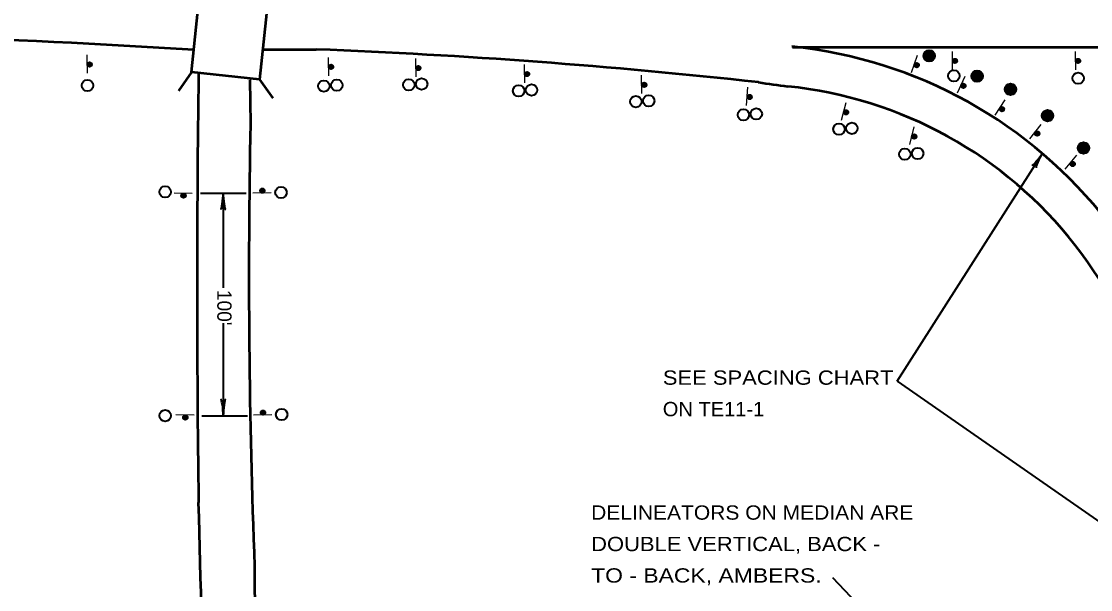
# Model space of a CAD drawing. Extents: x 393 to 1249, y -102 to 530.
# Drawn here: x 840.2 to 1022, y 229.1 to 325.7 of the extents above; entities that cross this region are included whole.
import ezdxf
from ezdxf.enums import TextEntityAlignment as Align

# ---------------------------------------------------------------- set-up
doc = ezdxf.new("R2010")
doc.units = 0
doc.header["$LTSCALE"] = 0.97
doc.layers.add('1', color=7, linetype='Continuous', lineweight=40)
doc.layers.add('4', color=7, linetype='Continuous', lineweight=25)

msp = doc.modelspace()

# ---------------------------------------------------------------- linework, layer by layer
at = {"layer": '1', "lineweight": 53}
for p, q in [((881.1775, 320.8992), (890.3153, 320.8992)), ((971.3426, 321.288), (1117.739, 321.288)), ((869.0836, 317.0209), (866.8533, 313.8363)), ((878.9941, 315.7335), (879.1249, 308.2401)), ((880.6838, 315.8016), (882.914, 312.6169))]:
    msp.add_line(p, q, dxfattribs=at)
at = {"layer": '1', "lineweight": 35}
for p, q in [((989.1144, 264.4924), (1013.9183, 303.3247)), ((870.6226, 296.465), (878.3986, 296.465)), ((874.4854, 296.465), (874.4854, 280.3528)), ((874.4854, 274.3552), (874.4854, 258.6495)), ((989.1144, 264.4924), (1038.9254, 229.9296)), ((870.8259, 258.6495), (878.6019, 258.6495)), ((978.1356, 231.1495), (1018.5944, 188.6576))]:
    msp.add_line(p, q, dxfattribs=at)
at = {"layer": '1', "lineweight": 53}
msp.add_lwpolyline([(871.7253, 342.1545), (883.3254, 340.935), (880.6838, 315.8016), (869.0836, 317.0209)], close=True, dxfattribs=at)
at = {"layer": '1'}
for centre, radius in [((994.5904, 319.7989), 0.972), ((994.5773, 319.8416), 0.8529), ((994.5646, 319.8162), 0.7878), ((994.5773, 319.7781), 0.7017), ((994.501, 319.524), 0.6228), ((994.5646, 319.8544), 0.5846), ((994.7171, 319.6637), 0.6414), ((994.5392, 319.7781), 0.4322), ((994.6408, 319.7018), 0.5216), ((994.59, 320.0322), 0.3831), ((994.5645, 319.8416), 0.3558), ((994.8187, 319.5621), 0.5762), ((851.7557, 318.3289), 0.3791), ((851.7461, 318.319), 0.35), ((851.7558, 318.3192), 0.3305), ((851.7748, 318.3487), 0.3402), ((851.7557, 318.3289), 0.3013), ((851.7557, 318.3289), 0.2819), ((851.7558, 318.3192), 0.2722), ((851.7558, 318.3192), 0.2527), ((851.7656, 318.3194), 0.2335), ((851.7753, 318.3195), 0.2138), ((851.7753, 318.3195), 0.1944), ((851.7562, 318.2998), 0.1555), ((851.7947, 318.3199), 0.175), ((851.756, 318.3095), 0.1069), ((851.8145, 318.3008), 0.1555), ((851.824, 318.3107), 0.1461), ((851.8339, 318.3011), 0.1166), ((851.8437, 318.3013), 0.0977), ((851.8534, 318.3015), 0.0778), ((851.7922, 318.4657), 0.00972), ((851.8728, 318.3018), 0.0583), ((851.8922, 318.3021), 0.0389), ((851.9117, 318.3025), 0.0194), ((892.8238, 317.9223), 0.3791), ((992.4465, 318.2232), 0.3791), ((992.4342, 318.2172), 0.35), ((992.4434, 318.214), 0.3305), ((992.4713, 318.2353), 0.3402), ((992.4465, 318.2232), 0.3013), ((992.4465, 318.2232), 0.2819), ((992.4434, 318.214), 0.2722), ((992.4434, 318.214), 0.2527), ((992.4526, 318.2109), 0.2335), ((992.4618, 318.2077), 0.2138), ((992.4618, 318.2077), 0.1944), ((992.4371, 318.1956), 0.1555), ((992.4801, 318.2014), 0.175), ((992.4402, 318.2048), 0.1069), ((992.4922, 318.1767), 0.1555), ((992.5046, 318.1827), 0.1461), ((992.5276, 318.3392), 0.00972), ((994.1579, 319.5748), 0.3923), ((994.59, 319.8416), 0.2049), ((994.59, 319.8162), 0.0508), ((998.9504, 318.9388), 0.3791), ((998.9409, 318.929), 0.35), ((998.9506, 318.9291), 0.3305), ((998.9695, 318.9586), 0.3402), ((998.9504, 318.9388), 0.3013), ((998.9504, 318.9388), 0.2819), ((998.9506, 318.9291), 0.2722), ((998.9506, 318.9291), 0.2527), ((998.9603, 318.9293), 0.2335), ((998.97, 318.9295), 0.2138), ((998.97, 318.9295), 0.1944), ((998.9509, 318.9097), 0.1555), ((998.9895, 318.9298), 0.175), ((998.9508, 318.9194), 0.1069), ((999.0092, 318.9107), 0.1555), ((999.0188, 318.9206), 0.1461), ((999.0287, 318.9111), 0.1166), ((999.0384, 318.9112), 0.0977), ((999.0481, 318.9114), 0.0778), ((998.9869, 319.0756), 0.00972), ((999.0675, 318.9117), 0.0583), ((999.087, 318.9121), 0.0389), ((999.1064, 318.9124), 0.0194), ((1019.8911, 318.9388), 0.3791), ((1019.8816, 318.929), 0.35), ((1019.8913, 318.9291), 0.3305), ((1019.9102, 318.9586), 0.3402), ((1019.8911, 318.9388), 0.3013), ((1019.8911, 318.9388), 0.2819), ((1019.8913, 318.9291), 0.2722), ((1019.8913, 318.9291), 0.2527), ((1019.901, 318.9293), 0.2335), ((1019.9107, 318.9295), 0.2138), ((1019.9107, 318.9295), 0.1944), ((1019.8916, 318.9097), 0.1555), ((1019.9301, 318.9298), 0.175), ((1019.8914, 318.9194), 0.1069), ((1019.9499, 318.9107), 0.1555), ((1019.9595, 318.9206), 0.1461), ((1019.9694, 318.9111), 0.1166), ((1019.9791, 318.9112), 0.0977), ((1019.9888, 318.9114), 0.0778), ((1019.9276, 319.0756), 0.00972), ((1020.0082, 318.9117), 0.0583), ((1020.0277, 318.9121), 0.0389), ((1020.0471, 318.9124), 0.0194), ((892.8143, 317.9124), 0.35), ((892.824, 317.9126), 0.3305), ((892.8429, 317.9421), 0.3402), ((892.8238, 317.9223), 0.3013), ((892.8238, 317.9223), 0.2819), ((892.824, 317.9126), 0.2722), ((892.824, 317.9126), 0.2527), ((892.8337, 317.9128), 0.2335), ((892.8434, 317.9129), 0.2138), ((892.8434, 317.9129), 0.1944), ((892.8243, 317.8931), 0.1555), ((892.8629, 317.9133), 0.175), ((892.8241, 317.9029), 0.1069), ((892.8826, 317.8942), 0.1555), ((892.8922, 317.904), 0.1461), ((892.9021, 317.8945), 0.1166), ((892.9118, 317.8947), 0.0977), ((892.9215, 317.8948), 0.0778), ((892.8603, 318.059), 0.00972), ((892.9409, 317.8952), 0.0583), ((892.9604, 317.8955), 0.0389), ((892.9798, 317.8959), 0.0194), ((907.6653, 317.719), 0.3791), ((907.6557, 317.7091), 0.35), ((907.6654, 317.7093), 0.3305), ((907.6844, 317.7388), 0.3402), ((907.6653, 317.719), 0.3013), ((907.6653, 317.719), 0.2819), ((907.6654, 317.7093), 0.2722), ((907.6654, 317.7093), 0.2527), ((907.6752, 317.7094), 0.2335), ((907.6849, 317.7096), 0.2138), ((907.6849, 317.7096), 0.1944), ((907.6658, 317.6898), 0.1555), ((907.7043, 317.7099), 0.175), ((907.6656, 317.6996), 0.1069), ((907.7241, 317.6909), 0.1555), ((907.7336, 317.7007), 0.1461), ((907.7435, 317.6912), 0.1166), ((907.7533, 317.6914), 0.0977), ((907.763, 317.6915), 0.0778), ((907.7018, 317.8557), 0.00972), ((907.7824, 317.6919), 0.0583), ((907.8018, 317.6922), 0.0389), ((907.8213, 317.6925), 0.0194), ((926.1663, 316.7024), 0.3791), ((926.1568, 316.6926), 0.35), ((926.1665, 316.6927), 0.3305), ((926.1854, 316.7222), 0.3402), ((926.1663, 316.7024), 0.3013), ((926.1663, 316.7024), 0.2819), ((926.1665, 316.6927), 0.2722), ((926.1665, 316.6927), 0.2527), ((926.1762, 316.6929), 0.2335), ((926.1859, 316.6931), 0.2138), ((926.1859, 316.6931), 0.1944), ((926.1668, 316.6733), 0.1555), ((926.2054, 316.6934), 0.175), ((926.1667, 316.683), 0.1069), ((926.2251, 316.6743), 0.1555), ((926.2347, 316.6842), 0.1461), ((926.2446, 316.6746), 0.1166), ((926.2543, 316.6748), 0.0977), ((926.264, 316.675), 0.0778), ((926.2028, 316.8392), 0.00972), ((926.2835, 316.6753), 0.0583), ((926.3029, 316.6757), 0.0389), ((926.3223, 316.676), 0.0194), ((992.5106, 318.1703), 0.1166), ((992.5198, 318.1672), 0.0977), ((992.529, 318.164), 0.0778), ((992.5473, 318.1577), 0.0583), ((992.5657, 318.1513), 0.0389), ((992.5841, 318.145), 0.0194), ((998.7836, 316.3927), 0.972), ((1002.7227, 316.3427), 0.972), ((1002.7096, 316.3854), 0.8529), ((1002.2902, 316.1186), 0.3923), ((1002.6969, 316.36), 0.7878), ((1002.7096, 316.3219), 0.7017), ((1002.6334, 316.0678), 0.6228), ((1002.6969, 316.3982), 0.5846), ((1002.8494, 316.2075), 0.6414), ((1002.6715, 316.3219), 0.4322), ((1002.7731, 316.2457), 0.5216), ((1002.7223, 316.576), 0.3831), ((1002.6969, 316.3855), 0.3558), ((1002.951, 316.1059), 0.5762), ((1002.7223, 316.3855), 0.2049), ((1019.9276, 315.9861), 0.972), ((851.3854, 314.7663), 0.972), ((891.6088, 314.6635), 0.972), ((893.8033, 314.805), 0.972), ((906.0438, 314.8667), 0.972), ((908.2383, 315.0083), 0.972), ((924.748, 313.8502), 0.972), ((926.9425, 313.9917), 0.972), ((946.0905, 314.8726), 0.3791), ((946.0809, 314.8628), 0.35), ((946.0906, 314.8629), 0.3305), ((946.1096, 314.8924), 0.3402), ((946.0905, 314.8726), 0.3013), ((946.0905, 314.8726), 0.2819), ((946.0906, 314.8629), 0.2722), ((946.0906, 314.8629), 0.2527), ((946.1004, 314.8631), 0.2335), ((946.1101, 314.8633), 0.2138), ((946.1101, 314.8633), 0.1944), ((946.091, 314.8435), 0.1555), ((946.1295, 314.8636), 0.175), ((946.0908, 314.8532), 0.1069), ((946.1493, 314.8445), 0.1555), ((946.1588, 314.8544), 0.1461), ((946.1687, 314.8449), 0.1166), ((946.1784, 314.845), 0.0977), ((946.1882, 314.8452), 0.0778), ((946.127, 315.0094), 0.00972), ((946.2076, 314.8455), 0.0583), ((946.227, 314.8459), 0.0389), ((946.2465, 314.8462), 0.0194), ((1000.3856, 314.7027), 0.3791), ((1000.3728, 314.6977), 0.35), ((1000.3817, 314.6938), 0.3305), ((1000.4113, 314.7125), 0.3402), ((1000.3856, 314.7027), 0.3013), ((1000.3856, 314.7027), 0.2819), ((1000.3817, 314.6938), 0.2722), ((1000.3817, 314.6938), 0.2527), ((1000.3906, 314.6898), 0.2335), ((1000.3994, 314.6859), 0.2138), ((1000.3994, 314.6859), 0.1944), ((1000.3738, 314.676), 0.1555), ((1000.4172, 314.678), 0.175), ((1000.3777, 314.6849), 0.1069), ((1000.4271, 314.6523), 0.1555), ((1000.4399, 314.6572), 0.1461), ((1000.4448, 314.6444), 0.1166), ((1000.4537, 314.6404), 0.0977), ((1000.4626, 314.6365), 0.0778), ((1000.4803, 314.6286), 0.0583), ((1000.4981, 314.6207), 0.0389), ((1000.4765, 314.8112), 0.00972), ((1002.7223, 316.36), 0.0508), ((1008.4154, 314.1063), 0.972), ((1008.4023, 314.149), 0.8529), ((1008.3896, 314.1236), 0.7878), ((1008.4023, 314.0855), 0.7017), ((1008.3896, 314.1618), 0.5846), ((1008.415, 314.3396), 0.3831), ((944.6722, 312.0204), 0.972), ((946.8667, 312.1619), 0.972), ((964.0243, 312.8095), 0.3791), ((964.0139, 312.8005), 0.35), ((964.0236, 312.7998), 0.3305), ((964.0451, 312.8275), 0.3402), ((964.0243, 312.8095), 0.3013), ((964.0243, 312.8095), 0.2819), ((964.0236, 312.7998), 0.2722), ((964.0236, 312.7998), 0.2527), ((964.0333, 312.7991), 0.2335), ((964.043, 312.7984), 0.2138), ((964.043, 312.7984), 0.1944), ((964.0223, 312.7804), 0.1555), ((964.0624, 312.7971), 0.175), ((964.023, 312.7901), 0.1069), ((964.0805, 312.7763), 0.1555), ((964.0908, 312.7853), 0.1461), ((964.0999, 312.775), 0.1166), ((964.1095, 312.7743), 0.0977), ((964.1192, 312.7736), 0.0778), ((964.0726, 312.9425), 0.00972), ((1000.5159, 314.6128), 0.0194), ((1007.9829, 313.8822), 0.3923), ((1008.326, 313.8314), 0.6228), ((1008.5421, 313.9711), 0.6414), ((1008.3642, 314.0855), 0.4322), ((1008.4658, 314.0092), 0.5216), ((1008.3895, 314.149), 0.3558), ((1008.6437, 313.8695), 0.5762), ((1008.415, 314.149), 0.2049), ((1008.415, 314.1236), 0.0508), ((964.1386, 312.7723), 0.0583), ((964.158, 312.7709), 0.0389), ((964.1774, 312.7695), 0.0194), ((1006.9475, 310.7465), 0.3791), ((1006.934, 310.7438), 0.35), ((1006.9421, 310.7384), 0.3305), ((1006.9745, 310.7517), 0.3402), ((1006.9475, 310.7465), 0.3013), ((1006.9475, 310.7465), 0.2819), ((962.9699, 309.784), 0.972), ((965.1644, 309.9256), 0.972), ((980.4372, 310.2066), 0.3791), ((980.4255, 310.1995), 0.35), ((980.4349, 310.1972), 0.3305), ((980.4608, 310.2207), 0.3402), ((980.4372, 310.2066), 0.3013), ((980.4372, 310.2066), 0.2819), ((980.4349, 310.1972), 0.2722), ((980.4349, 310.1972), 0.2527), ((980.4443, 310.1948), 0.2335), ((980.4538, 310.1925), 0.2138), ((980.4538, 310.1925), 0.1944), ((980.4302, 310.1783), 0.1555), ((980.4726, 310.1878), 0.175), ((980.4325, 310.1877), 0.1069), ((980.4868, 310.1642), 0.1555), ((980.4986, 310.1713), 0.1461), ((980.5056, 310.1595), 0.1166), ((980.5151, 310.1571), 0.0977), ((980.5245, 310.1548), 0.0778), ((980.5434, 310.1501), 0.0583), ((980.5079, 310.3292), 0.00972), ((980.5622, 310.1454), 0.0389), ((980.5811, 310.1407), 0.0194), ((1006.9421, 310.7384), 0.2722), ((1006.9421, 310.7384), 0.2527), ((1006.9501, 310.733), 0.2335), ((1006.9582, 310.7275), 0.2138), ((1006.9582, 310.7275), 0.1944), ((1006.9312, 310.7223), 0.1555), ((1006.9743, 310.7167), 0.175), ((1006.9796, 310.6897), 0.1555), ((1006.9366, 310.7303), 0.1069), ((1006.993, 310.6923), 0.1461), ((1006.9957, 310.6788), 0.1166), ((1007.0037, 310.6734), 0.0977), ((1007.0118, 310.6679), 0.0778), ((1007.0279, 310.6571), 0.0583), ((1007.044, 310.6462), 0.0389), ((1007.0601, 310.6353), 0.0194), ((1007.0558, 310.8375), 0.00972), ((1014.718, 309.6335), 0.972), ((1014.7048, 309.6762), 0.8529), ((1014.2855, 309.4094), 0.3923), ((1014.6921, 309.6508), 0.7878), ((1014.7048, 309.6127), 0.7017), ((1014.6286, 309.3585), 0.6228), ((1014.6921, 309.6889), 0.5846), ((1014.8446, 309.4983), 0.6414), ((1014.6667, 309.6127), 0.4322), ((1014.7683, 309.5364), 0.5216), ((1014.7175, 309.8668), 0.3831), ((1014.6921, 309.6762), 0.3558), ((1014.9463, 309.3967), 0.5762), ((1014.7176, 309.6762), 0.2049), ((1014.7175, 309.6508), 0.0508), ((979.2346, 307.3443), 0.972), ((981.4291, 307.4859), 0.972), ((992.0217, 306.0843), 0.3791), ((992.0099, 306.0772), 0.35), ((992.0194, 306.0748), 0.3305), ((992.0453, 306.0984), 0.3402), ((992.0217, 306.0843), 0.3013), ((992.0217, 306.0843), 0.2819), ((992.0194, 306.0748), 0.2722), ((992.0194, 306.0748), 0.2527), ((992.0288, 306.0725), 0.2335), ((992.0382, 306.0701), 0.2138), ((992.0382, 306.0701), 0.1944), ((992.0147, 306.056), 0.1555), ((992.0571, 306.0654), 0.175), ((992.017, 306.0654), 0.1069), ((992.0712, 306.0419), 0.1555), ((992.083, 306.049), 0.1461), ((992.0901, 306.0372), 0.1166), ((992.0995, 306.0348), 0.0977), ((992.109, 306.0325), 0.0778), ((992.1278, 306.0278), 0.0583), ((992.0924, 306.2069), 0.00972), ((992.1467, 306.0231), 0.0389), ((992.1656, 306.0184), 0.0194), ((1012.9435, 306.5887), 0.3791), ((1012.9299, 306.5873), 0.35), ((1012.9374, 306.5812), 0.3305), ((1012.9709, 306.5916), 0.3402), ((1012.9435, 306.5887), 0.3013), ((1012.9435, 306.5887), 0.2819), ((1012.9374, 306.5812), 0.2722), ((1012.9374, 306.5812), 0.2527), ((1012.945, 306.575), 0.2335), ((1012.9525, 306.5689), 0.2138), ((1012.9525, 306.5689), 0.1944), ((1012.9252, 306.566), 0.1555), ((1012.9676, 306.5567), 0.175), ((1012.9705, 306.5293), 0.1555), ((1012.9313, 306.5736), 0.1069), ((1012.9842, 306.5308), 0.1461), ((1012.9856, 306.5171), 0.1166), ((1012.9932, 306.511), 0.0977), ((1013.0007, 306.5049), 0.0778), ((1013.0158, 306.4926), 0.0583), ((1013.0309, 306.4804), 0.0389), ((1013.046, 306.4682), 0.0194), ((1013.0594, 306.67), 0.00972), ((990.4164, 303.0749), 0.972), ((992.6109, 303.2165), 0.972), ((1020.8172, 304.1442), 0.972), ((1020.804, 304.1869), 0.8529), ((1020.3847, 303.9201), 0.3923), ((1020.7913, 304.1615), 0.7878), ((1020.8041, 304.1234), 0.7017), ((1020.7278, 303.8693), 0.6228), ((1020.7913, 304.1997), 0.5846), ((1020.9438, 304.009), 0.6414), ((1020.7659, 304.1234), 0.4322), ((1020.8676, 304.0471), 0.5216), ((1020.8167, 304.3775), 0.3831), ((1020.7913, 304.1869), 0.3558), ((1021.0455, 303.9074), 0.5762), ((1020.8168, 304.1869), 0.2049), ((1020.8167, 304.1615), 0.0508), ((1018.9853, 301.4181), 0.3791), ((1018.9716, 301.4166), 0.35), ((1018.9792, 301.4105), 0.3305), ((1019.0126, 301.4209), 0.3402), ((1018.9853, 301.4181), 0.3013), ((1018.9853, 301.4181), 0.2819), ((1018.9792, 301.4105), 0.2722), ((1018.9792, 301.4105), 0.2527), ((1018.9867, 301.4044), 0.2335), ((1018.9943, 301.3983), 0.2138), ((1018.9943, 301.3983), 0.1944), ((1018.9669, 301.3954), 0.1555), ((1019.0094, 301.386), 0.175), ((1019.0123, 301.3587), 0.1555), ((1018.9731, 301.4029), 0.1069), ((1019.0259, 301.3601), 0.1461), ((1019.0274, 301.3465), 0.1166), ((1019.0349, 301.3403), 0.0977), ((1019.0425, 301.3342), 0.0778), ((1019.0576, 301.322), 0.0583), ((1019.0727, 301.3098), 0.0389), ((1019.0878, 301.2975), 0.0194), ((1019.1011, 301.4993), 0.00972), ((864.6005, 296.6719), 0.972), ((881.1495, 296.8831), 0.3791), ((881.1297, 296.9022), 0.3402), ((881.1594, 296.8736), 0.35), ((881.1592, 296.8833), 0.3305), ((881.1495, 296.8831), 0.3013), ((881.1495, 296.8831), 0.2819), ((881.1592, 296.8833), 0.2722), ((881.1592, 296.8833), 0.2527), ((881.159, 296.893), 0.2335), ((881.1589, 296.9027), 0.2138), ((881.1589, 296.9027), 0.1944), ((881.1585, 296.9222), 0.175), ((881.0128, 296.9196), 0.00972), ((881.1677, 296.9515), 0.1461), ((881.1776, 296.9419), 0.1555), ((881.1786, 296.8836), 0.1555), ((881.1773, 296.9614), 0.1166), ((881.1689, 296.8835), 0.1069), ((881.1771, 296.9711), 0.0977), ((881.177, 296.9808), 0.0778), ((881.1766, 297.0003), 0.0583), ((881.1763, 297.0197), 0.0389), ((881.1759, 297.0391), 0.0194), ((884.3213, 296.5703), 0.972), ((867.7312, 296.0491), 0.3791), ((867.7114, 296.0301), 0.3402), ((867.7411, 296.0587), 0.35), ((867.7409, 296.049), 0.3305), ((867.7312, 296.0491), 0.3013), ((867.7312, 296.0491), 0.2819), ((867.7409, 296.049), 0.2722), ((867.7409, 296.049), 0.2527), ((867.7407, 296.0393), 0.2335), ((867.7406, 296.0295), 0.2138), ((867.7406, 296.0295), 0.1944), ((867.7402, 296.0101), 0.175), ((867.5945, 296.0127), 0.00972), ((867.7494, 295.9808), 0.1461), ((867.7593, 295.9903), 0.1555), ((867.7604, 296.0486), 0.1555), ((867.759, 295.9709), 0.1166), ((867.7506, 296.0488), 0.1069), ((867.7588, 295.9612), 0.0977), ((867.7587, 295.9515), 0.0778), ((867.7583, 295.932), 0.0583), ((867.758, 295.9126), 0.0389), ((867.7576, 295.8931), 0.0194), ((864.6005, 258.6534), 0.972), ((868.0362, 258.3355), 0.3791), ((868.0164, 258.3165), 0.3402), ((868.046, 258.3451), 0.35), ((868.0459, 258.3354), 0.3305), ((868.0362, 258.3355), 0.3013), ((868.0362, 258.3355), 0.2819), ((868.0459, 258.3354), 0.2722), ((868.0459, 258.3354), 0.2527), ((868.0457, 258.3257), 0.2335), ((868.0455, 258.3159), 0.2138), ((868.0455, 258.3159), 0.1944), ((868.0452, 258.2965), 0.175), ((867.8994, 258.2991), 0.00972), ((868.0544, 258.2672), 0.1461), ((868.0643, 258.2767), 0.1555), ((868.0653, 258.335), 0.1555), ((868.064, 258.2573), 0.1166), ((868.0556, 258.3352), 0.1069), ((868.0638, 258.2476), 0.0977), ((868.0636, 258.2379), 0.0778), ((868.0633, 258.2184), 0.0583), ((881.2511, 259.1695), 0.3791), ((881.2314, 259.1886), 0.3402), ((881.261, 259.16), 0.35), ((881.2609, 259.1697), 0.3305), ((881.2511, 259.1695), 0.3013), ((881.2511, 259.1695), 0.2819), ((881.2609, 259.1697), 0.2722), ((881.2609, 259.1697), 0.2527), ((881.2607, 259.1794), 0.2335), ((881.2605, 259.1891), 0.2138), ((881.2605, 259.1891), 0.1944), ((881.2602, 259.2086), 0.175), ((881.1144, 259.206), 0.00972), ((881.2694, 259.2379), 0.1461), ((881.2793, 259.2283), 0.1555), ((881.2803, 259.17), 0.1555), ((881.2789, 259.2478), 0.1166), ((881.2706, 259.1699), 0.1069), ((881.2788, 259.2575), 0.0977), ((881.2786, 259.2672), 0.0778), ((881.2783, 259.2867), 0.0583), ((881.2779, 259.3061), 0.0389), ((881.2776, 259.3255), 0.0194), ((884.423, 258.8567), 0.972), ((868.0629, 258.199), 0.0389), ((868.0626, 258.1795), 0.0194)]:
    msp.add_circle(centre, radius, dxfattribs=at)
at = {"layer": '1', "lineweight": 53}
for centre, radius, start, end in [((775.0829, -1146.6068), 1470.4337, 86.31926, 93.74555), ((848.6452, -747.1034), 1068.8151, 83.72252, 87.76563), ((963.3586, 243.8401), 77.9235, 351.15916, 84.21058), ((3508.5352, 280.3265), 2638.4955, 179.20845, 180.79155), ((996.4134, 516.6783), 203.732, 261.27626, 262.70179), ((2143.7838, 282.396), 1264.9229, 178.82928, 182.23643), ((-1822.5792, 162.2285), 2694.1082, 358.26332, 1.73668), ((935.2205, 230.8084), 55.4409, 177.69851, 226.22678)]:
    msp.add_arc(centre, radius, start, end, dxfattribs=at)
for centre, major_axis, ratio, start_param, end_param in [((963.3586, 243.8401), (-70.7919, 7.1776), 0.999504, 3.09935947, 4.71238898), ((953.2504, 242.7846), (-80.225, 11.5377), 0.914497, 0.93119967, 3.17475561), ((953.2504, 242.7846), (-86.4787, 12.4371), 0.928319, 2.3193134, 3.14264567)]:
    msp.add_ellipse(centre, major_axis=major_axis, ratio=ratio, start_param=start_param, end_param=end_param, dxfattribs=at)
at = {"layer": '1'}
for centre, major_axis, ratio, start_param, end_param in [((1013.1586, 302.5175), (-1.0629, -1.3469), 0.07063, 6.28230741, 8.55970261), ((1013.5736, 302.2863), (0.8064, 1.5445), 0.122415, 0.89635335, 3.14159265), ((874.2797, 295.3758), (-0.1707, -1.7073), 0.07063, 6.28230741, 8.55970261), ((874.754, 295.4043), (-0.1518, 1.7357), 0.122415, 0.89635335, 3.14159265), ((874.2168, 259.7102), (0.1518, -1.7357), 0.122415, 0.89635335, 3.14159265), ((874.6911, 259.7387), (0.1707, 1.7073), 0.07063, 6.28230741, 8.55970261)]:
    msp.add_ellipse(centre, major_axis=major_axis, ratio=ratio, start_param=start_param, end_param=end_param, dxfattribs=at)
at = {"layer": '4'}
for p, q in [((998.5681, 317.4449), (998.5138, 320.5548)), ((1019.5089, 317.4449), (1019.4544, 320.5548)), ((851.3734, 316.835), (851.3191, 319.9449)), ((892.4416, 316.4283), (892.3871, 319.5383)), ((907.283, 316.225), (907.2286, 319.335)), ((925.7841, 315.2085), (925.7297, 318.3184)), ((991.5764, 316.9502), (992.589, 319.891)), ((945.7083, 313.3787), (945.6538, 316.4886)), ((999.4078, 313.5104), (1000.673, 316.3518)), ((963.5133, 311.3546), (963.7302, 314.4574)), ((979.6814, 308.8626), (980.4339, 311.8805)), ((1005.7775, 309.7421), (1007.5168, 312.3207)), ((991.2659, 304.7402), (992.0183, 307.7583)), ((1011.6904, 305.6901), (1013.6479, 308.1073)), ((1017.7322, 300.5195), (1019.6897, 302.9366)), ((869.2253, 296.4314), (866.1151, 296.4856)), ((882.6436, 296.5008), (879.5333, 296.4466)), ((869.5303, 258.7178), (866.42, 258.772)), ((882.7453, 258.7872), (879.635, 258.733))]:
    msp.add_line(p, q, dxfattribs=at)
for centre in [(851.7555, 318.3386), (892.8236, 317.932), (992.4497, 318.2324), (998.9502, 318.9486), (1019.8909, 318.9486), (907.6651, 317.7287), (926.1662, 316.7122), (946.0903, 314.8824), (1000.3896, 314.7115), (964.025, 312.8192), (1006.9529, 310.7545), (980.4396, 310.216), (992.0241, 306.0937), (1012.9496, 306.5963), (1018.9914, 301.4256), (881.1398, 296.883), (867.7215, 296.0493), (868.0264, 258.3357), (881.2414, 259.1694)]:
    msp.add_circle(centre, 0.3985, dxfattribs=at)

# ---------------------------------------------------------------- texts
at = {"layer": '1'}
msp.add_text("100'", height=2.43, rotation=270, dxfattribs=at).set_placement((873.4737, 276.9982), align=Align.CENTER)
for s, width, p in [('SEE SPACING CHART', 1.15, (949.26, 263.9014)), ('ON TE11-1', 1.05, (949.26, 258.5554)), ('DELINEATORS ON MEDIAN ARE', 1.1, (937.067, 240.9732)), ('DOUBLE VERTICAL, BACK -', 1.15, (937.067, 235.6272)), ('TO - BACK, AMBERS.', 1.2, (937.067, 230.2812))]:
    msp.add_text(s, height=2.43, dxfattribs=dict(at, width=width)).set_placement(p)

doc.saveas('drawing.dxf')
